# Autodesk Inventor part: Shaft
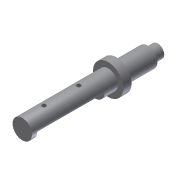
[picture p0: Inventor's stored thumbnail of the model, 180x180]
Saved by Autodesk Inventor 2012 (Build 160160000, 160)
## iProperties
Created: 2009-04
Part Number: Shaft
Document SubType Name: Modeling
Designer: Sham
Density: 1 g/cm^3
Material: Default
Author: Sham
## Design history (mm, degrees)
sketch "Sketch1"
  geometry: C1 r 18.75 at (511.175, 103.188)
  constraints: 1 centre point
  dimensions: "d0" = 37.5 diameter of C1
extrude "Extrusion1" new body sketch "Sketch1" distance "d1" = 28.9; taper "d2" = 0 deg
sketch "Sketch2"
  geometry: C1 r 28 at (0, 0)
  constraints: 1 centre point
  dimensions: "d3" = 56 diameter of C1
extrude "Extrusion2" join sketch "Sketch2" distance "d4" = 89.8; taper "d5" = 0 deg
sketch "Sketch3"
  geometry: C1 r 43.6 at (0, 0)
  constraints: 1 centre point
  dimensions: "d6" = 87.2 diameter of C1
extrude "Extrusion3" join sketch "Sketch3" distance "d7" = 24; taper "d8" = 0 deg
sketch "Sketch4"
  geometry: C1 r 43.6 at (0, 0) reference; C2 r 28 at (0, 0)
  constraints: 1 centre point, 1 coincident
  dimensions: "d9" = 56 diameter of C2
extrude "Extrusion4" join sketch "Sketch4" distance "d10" = 247.1; taper "d11" = 0 deg
workplane "Work Plane1"
sketch "Sketch5"
  geometry: L1 (28, 0)-(-28, 0); C1 r 43.6 at (0, 0) reference; A1 r 28 centre (0, 0) between (-28, 0) and (28, 0)
  constraints: 2 end point, 2 point on circle, 1 centre point, 1 concentric, 1 horizontal
  dimensions: "d13" = 56 diameter of A1
extrude "Extrusion5" cut sketch "Sketch5" distance "d14" = 193.8; taper "d15" = 0 deg
hole "Hole1" diameter "d18" = 12.5; stored, may be unused: countersink angle "d22" = 90 deg, drill point angle "d24" = 118 deg; dims "d16" = 28, "d17" = 46.9, "d19" = 6, "d20" = 4, "d21" = 2, "d23" = 8
pattern_linear "Rectangular Pattern1" dims "d27" = 100
body "Solid1"
other parameters: "d12" = -15.1
